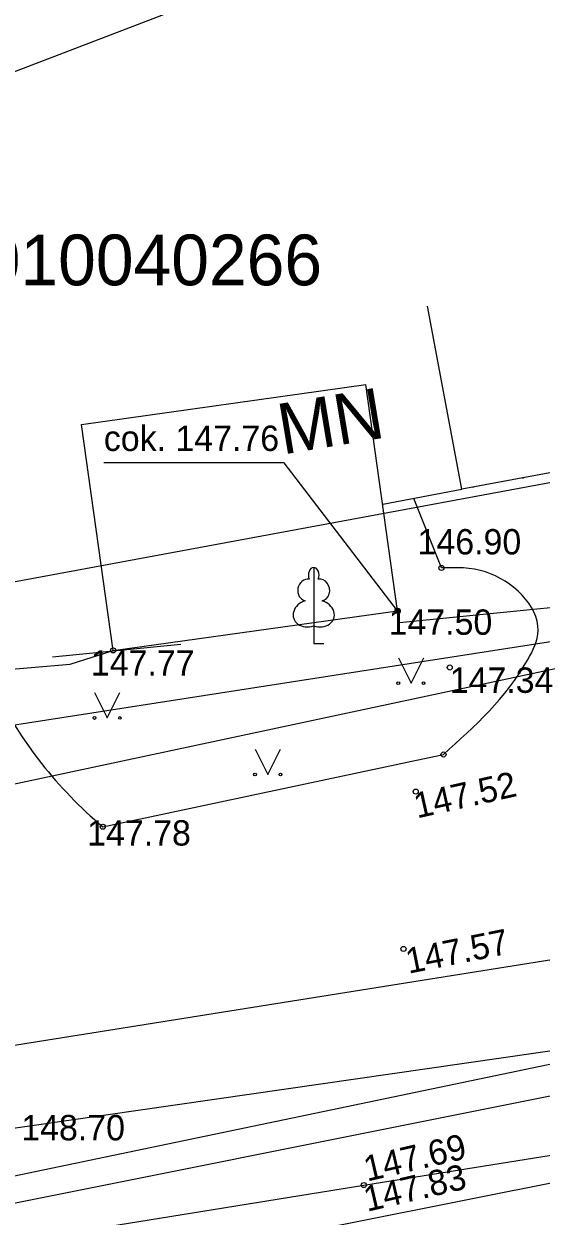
# Model space of a CAD drawing. Extents: x 728492 to 729038, y 272968 to 273171.
# Drawn here: x 728641.64 to 728651.84, y 273065.2 to 273088.71 of the extents above; entities that cross this region are included whole.
import ezdxf

# ---------------------------------------------------------------- set-up
doc = ezdxf.new("R2010")
doc.units = 0
for name, color, linetype in [('APGR_SARK_####_####_#', 7, 'Continuous'), ('BUVE_BDET_####_####_#', 7, 'Continuous'), ('BUVE_BDET_####_TKST_#', 7, 'Continuous'), ('BUVE_EKAS_####_####_#', 7, 'Continuous'), ('BUVE_EKAS_RAKS_TKST_#', 7, 'Continuous'), ('CELI_CAPM_####_####_#', 7, 'Continuous'), ('CELI_CMAL_####_####_#', 7, 'Continuous'), ('ELEK_VADP_ZSPR_####_#', 7, 'Continuous'), ('ELEK_VADV_ZSPR_####_#', 7, 'Continuous'), ('NORB_ZOGS_ZMET_####_#', 7, 'Continuous'), ('NORB_ZOGS_ZSTP_####_#', 7, 'Continuous'), ('RAMI_UZMR_####_####_#', 7, 'Continuous'), ('RELJ_AATZ_####_TKST_#', 7, 'Continuous'), ('RELJ_ELEM_####_####_#', 7, 'Continuous'), ('RELJ_NOGA_####_####_#', 7, 'Continuous'), ('ROBZ_KADS_####_TKST_#', 7, 'Continuous'), ('ROBZ_UZMR_####_####_#', 7, 'Continuous'), ('SAKT_VADV_PKAB_####_#', 7, 'Continuous'), ('SILT_VADP_UDEN_####_#', 7, 'Continuous'), ('SKAN_VADP_PAST_####_#', 7, 'Continuous'), ('TERT_ELEM_####_####_#', 7, 'Continuous'), ('UDTK_VADP_UDEN_####_#', 7, 'Continuous')]:
    doc.layers.add(name, color=color, linetype=linetype)

msp = doc.modelspace()

# ---------------------------------------------------------------- linework, layer by layer
at = {"layer": 'APGR_SARK_####_####_#'}
msp.add_lwpolyline([(728659.143, 273080.982), (728541.407, 273059.185)], dxfattribs=at)
at = {"layer": 'BUVE_BDET_####_####_#'}
for points in [[(728644.168, 273080.055), (728643.214, 273080.055)], [(728649.007, 273077.141), (728646.773, 273080.055), (728644.168, 273080.055)]]:
    msp.add_lwpolyline(points, dxfattribs=at)
at = {"layer": 'BUVE_EKAS_####_####_#'}
for p, q in [((728650.273, 273079.535), (728649.6, 273083.147)), ((728642.773, 273080.814), (728648.384, 273081.598)), ((728649.007, 273077.141), (728648.384, 273081.598)), ((728643.396, 273076.357), (728642.773, 273080.814)), ((728654.187, 273080.264), (728650.273, 273079.535)), ((728643.396, 273076.357), (728649.007, 273077.141))]:
    msp.add_line(p, q, dxfattribs=at)
at = {"layer": 'CELI_CAPM_####_####_#'}
msp.add_line((728648.342, 273065.816), (728664.349, 273068.383), dxfattribs=at)
msp.add_lwpolyline([(728630.786, 273062.984), (728648.342, 273065.816), (728648.342, 273065.816)], dxfattribs=at)
at = {"layer": 'CELI_CMAL_####_####_#'}
for p, q in [((728649.872, 273077.985), (728649.327, 273079.355)), ((728649.503, 273074.219), (728649.913, 273074.306)), ((728643.192, 273072.882), (728649.503, 273074.219))]:
    msp.add_line(p, q, dxfattribs=at)
msp.add_arc((728648.689, 273079.412), 8.535, 206.5697, 229.9071, dxfattribs=at)
msp.add_spline([(728649.913, 273074.306), (728651.57, 273076.164), (728651.779, 273076.75), (728650.743, 273077.904), (728649.872, 273077.985)], degree=3, dxfattribs=at)
at = {"layer": 'ELEK_VADP_ZSPR_####_#'}
for points in [[(728654.729, 273077.464), (728649.047, 273076.903)], [(728644.73, 273076.476), (728642.205, 273076.227)]]:
    msp.add_lwpolyline(points, dxfattribs=at)
at = {"layer": 'ELEK_VADV_ZSPR_####_#'}
msp.add_line((728617.923, 273068.708), (728666.081, 273078.979), dxfattribs=at)
at = {"layer": 'NORB_ZOGS_ZMET_####_#'}
msp.add_lwpolyline([(728641.005, 273075.952), (728642.549, 273076.089), (728643.396, 273076.357)], dxfattribs=at)
at = {"layer": 'NORB_ZOGS_ZSTP_####_#'}
msp.add_lwpolyline([(728648.714, 273079.238), (728650.273, 273079.535)], dxfattribs=at)
at = {"layer": 'RAMI_UZMR_####_####_#'}
msp.add_lwpolyline([(728726.814, 273102.175), (728686.914, 273096.216), (728659.323, 273094.615), (728619.629, 273079.414), (728545.121, 273067.256)], dxfattribs=at)
at = {"layer": 'RELJ_ELEM_####_####_#'}
for centre in [(728649.872, 273077.985), (728649.872, 273077.985), (728649.007, 273077.141), (728649.01, 273077.136), (728643.396, 273076.357), (728650.036, 273076.021), (728649.913, 273074.306), (728649.365, 273073.574), (728643.192, 273072.882), (728649.125, 273070.472), (728648.342, 273065.816)]:
    msp.add_circle(centre, 0.05, dxfattribs=at)
at = {"layer": 'RELJ_NOGA_####_####_#'}
for p, q in [((728651.481, 273079.76), (728651.483, 273079.75)), ((728650.498, 273079.577), (728650.5, 273079.567)), ((728650.99, 273079.669), (728650.99, 273079.666))]:
    msp.add_line(p, q, dxfattribs=at)
at = {"layer": 'ROBZ_UZMR_####_####_#'}
msp.add_line((728664.052, 273078.4), (728634.713, 273073.836), dxfattribs=at)
at = {"layer": 'SAKT_VADV_PKAB_####_#'}
msp.add_line((728635.134, 273062.502), (728677.472, 273070.914), dxfattribs=at)
at = {"layer": 'SILT_VADP_UDEN_####_#'}
for points in [[(728554.662, 273032.952), (728554.113, 273035.473), (728554.267, 273035.774), (728581.419, 273054.878), (728582.018, 273055.208), (728610.89, 273060.328), (728630.183, 273063.782), (728638.039, 273065.289), (728652.893, 273068.386), (728653.925, 273076.859), (728654.802, 273077.089)], [(728555.193, 273032.922), (728554.64, 273035.405), (728554.656, 273035.436), (728581.684, 273054.453), (728582.187, 273054.73), (728610.978, 273059.835), (728630.274, 273063.29), (728638.144, 273064.8), (728653.493, 273067.873), (728654.384, 273076.462), (728654.897, 273076.597)]]:
    msp.add_lwpolyline(points, dxfattribs=at)
at = {"layer": 'SKAN_VADP_PAST_####_#'}
msp.add_lwpolyline([(728616.534, 273064.605), (728669.124, 273072.987)], dxfattribs=at)
at = {"layer": 'TERT_ELEM_####_####_#'}
for p, q in [((728647.354, 273076.841), (728647.354, 273076.494)), ((728647.354, 273076.494), (728647.554, 273076.494)), ((728649.023, 273076.212), (728649.273, 273075.712)), ((728649.273, 273075.712), (728649.523, 273076.212)), ((728643.029, 273075.526), (728643.279, 273075.026)), ((728643.279, 273075.026), (728643.529, 273075.526)), ((728646.197, 273074.412), (728646.447, 273073.912)), ((728646.447, 273073.912), (728646.697, 273074.412))]:
    msp.add_line(p, q, dxfattribs=at)
for points in [[(728647.354, 273077.994), (728647.354, 273076.841)], [(728647.444, 273077.762), (728647.443, 273077.763)]]:
    msp.add_lwpolyline(points, dxfattribs=at)
for centre, radius in [((728649.022, 273075.711), 0.028), ((728649.522, 273075.711), 0.0263), ((728643.029, 273075.026), 0.028), ((728643.529, 273075.026), 0.0263), ((728646.197, 273073.911), 0.028), ((728646.697, 273073.911), 0.0263)]:
    msp.add_circle(centre, radius, dxfattribs=at)
for centre, major_axis, ratio, start_param, end_param in [((728647.354, 273077.844), (0, -0.15), 0.707107, 3.14537, 5.287485), ((728647.354, 273077.844), (0, -0.15), 0.707107, 0.995701, 3.137816), ((728647.226, 273077.549), (-0.039, -0.212), 0.861323, 3.141593, 6.283185), ((728647.482, 273077.549), (0.039, -0.212), 0.861323, 0, 3.141593), ((728647.264, 273077.087), (0.307, 0.095), 0.814445, 1.570796, 4.752015), ((728647.444, 273077.087), (-0.307, 0.095), 0.814445, 1.531171, 4.712389)]:
    msp.add_ellipse(centre, major_axis=major_axis, ratio=ratio, start_param=start_param, end_param=end_param, dxfattribs=at)
at = {"layer": 'UDTK_VADP_UDEN_####_#'}
msp.add_lwpolyline([(728536.753, 273051.73), (728562.041, 273055.954), (728585.763, 273058.374), (728605.397, 273061.619), (728606.945, 273061.767), (728607.469, 273061.897), (728613.688, 273063.022), (728614.11, 273063.005), (728657.437, 273069.243)], dxfattribs=at)

# ---------------------------------------------------------------- texts
at = {"layer": 'BUVE_BDET_####_TKST_#'}
msp.add_text('cok. 147.76', height=0.49999, dxfattribs=at).set_placement((728643.214, 273080.29))
at = {"layer": 'BUVE_EKAS_RAKS_TKST_#'}
msp.add_text('MN', height=1, rotation=9.474, dxfattribs=at).set_placement((728646.739, 273080.216))
at = {"layer": 'RELJ_AATZ_####_TKST_#'}
for s, p in [(' 146.90', (728649.216, 273078.25)), (' 147.50', (728648.645, 273076.666)), (' 147.77', (728642.773, 273075.862)), ('147.34', (728650.036, 273075.521)), (' 147.78', (728642.7, 273072.51)), ('148.70', (728641.586, 273066.699))]:
    msp.add_text(s, height=0.5, dxfattribs=at).set_placement(p)
for s, rotation, p in [('147.52', 12.6142, (728649.393, 273073.044)), ('147.57', 11.3251, (728649.223, 273069.982)), ('147.69', 13.1269, (728648.407, 273065.885)), ('147.83', 13.1269, (728648.407, 273065.289))]:
    msp.add_text(s, height=0.5, rotation=rotation, dxfattribs=at).set_placement(p)
at = {"layer": 'ROBZ_KADS_####_TKST_#'}
msp.add_text('68010040266', height=1, dxfattribs=at).set_placement((728639.338, 273083.556))

doc.saveas('drawing.dxf')
